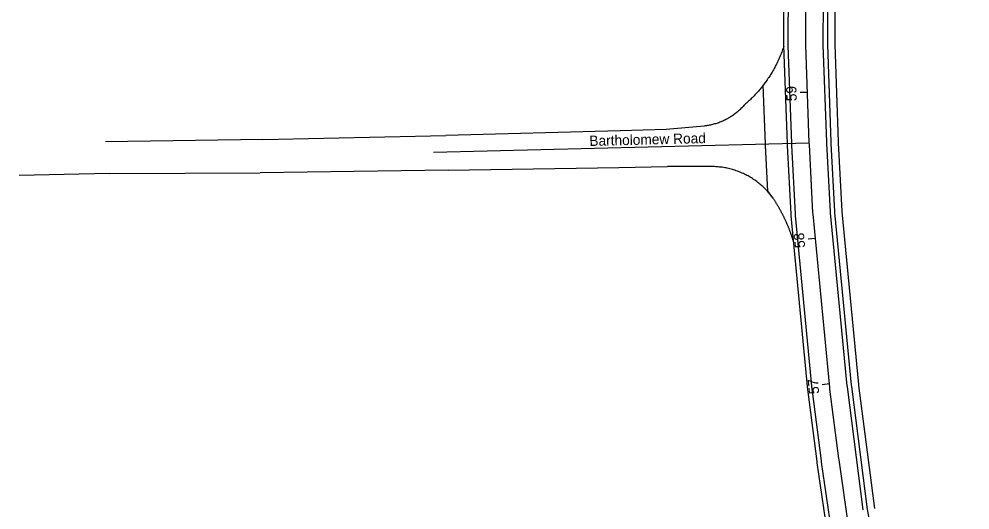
# Model space of a CAD drawing. Extents: x 2318076 to 2324211, y 613525 to 629939.
# Drawn here: x 2318076 to 2318726, y 620517 to 620852 of the extents above; entities that cross this region are included whole.
import ezdxf

# ---------------------------------------------------------------- set-up
doc = ezdxf.new("R2010")
doc.units = 0
for name, color, linetype in [('GE_P_CL_50', 7, 'Continuous'), ('GE_X_CL_50', 7, 'Continuous'), ('PV_P_EOP', 7, 'Continuous'), ('PV_P_Shoulder', 7, 'Continuous'), ('RD_X_GR_Rt', 7, 'Continuous'), ('RS_Raster1', 7, 'Continuous'), ('TX_P_1', 7, 'Continuous')]:
    doc.layers.add(name, color=color, linetype=linetype)

msp = doc.modelspace()

# ---------------------------------------------------------------- linework, layer by layer
at = {"layer": 'GE_P_CL_50'}
for p, q in [((2318615.25, 620802.3), (2318610.26, 620802.12)), ((2318620.66, 620702.47), (2318615.68, 620701.99)), ((2318630.24, 620602.93), (2318625.26, 620602.45))]:
    msp.add_line(p, q, dxfattribs=at)
msp.add_lwpolyline([(2318643.51, 620504.66), (2318636.81, 620551.04), (2318636.68, 620552.01), (2318630.59, 620599.46), (2318630.48, 620600.43), (2318619.07, 620719), (2318619.01, 620719.99), (2318616.54, 620766.75), (2318616.5, 620767.74), (2318614.09, 620834.59), (2318614.09, 620835.59), (2318614.08, 620836.59), (2318614.07, 620837.58), (2318614.09, 620849.48), (2318614.1, 620850.47), (2318614.18, 620857.38)], dxfattribs=at)
at = {"layer": 'GE_X_CL_50'}
msp.add_line((2318359.77, 620761.32), (2318616.5, 620767.74), dxfattribs=at)
at = {"layer": 'PV_P_EOP'}
for points in [[(2318631.64, 620502.89), (2318624.93, 620549.37), (2318624.78, 620550.44), (2318618.68, 620597.98), (2318618.54, 620599.14), (2318607.11, 620718.03), (2318607.03, 620719.28), (2318604.55, 620766.19), (2318604.51, 620767.29), (2318602.1, 620834.32), (2318602.09, 620835.48), (2318602.08, 620836.49), (2318602.07, 620837.55), (2318602.09, 620849.54), (2318602.1, 620850.59), (2318602.18, 620857.53)], [(2318653.3, 620516.78), (2318642.5, 620600.94), (2318642.41, 620601.72), (2318631.03, 620719.97), (2318630.99, 620720.7), (2318628.52, 620767.31), (2318628.49, 620768.2), (2318626.09, 620834.86), (2318626.08, 620835.69), (2318626.08, 620836.68), (2318626.07, 620837.62), (2318626.09, 620849.42), (2318626.1, 620850.35), (2318626.18, 620857.23)], [(2318599.11, 620833.88), (2318598.88, 620833.18), (2318598.59, 620832.34), (2318598.3, 620831.5), (2318597.99, 620830.66), (2318597.68, 620829.83), (2318597.36, 620828.99), (2318597.03, 620828.17), (2318596.69, 620827.34), (2318596.34, 620826.52), (2318595.99, 620825.7), (2318595.63, 620824.89), (2318595.25, 620824.08), (2318594.88, 620823.27), (2318594.49, 620822.47), (2318594.09, 620821.67), (2318593.69, 620820.87), (2318593.28, 620820.08), (2318592.86, 620819.29), (2318592.43, 620818.51), (2318592, 620817.73), (2318591.56, 620816.96), (2318591.11, 620816.19), (2318590.65, 620815.43), (2318590.18, 620814.67), (2318589.71, 620813.91), (2318589.23, 620813.16), (2318588.74, 620812.41), (2318588.24, 620811.67), (2318587.74, 620810.94), (2318585.07, 620807.12)], [(2318588.2, 620734.8), (2318586.55, 620766.05), (2318586.51, 620767.17), (2318585.07, 620807.12)], [(2318591.8, 620729.86), (2318588.2, 620734.8)], [(2318605.83, 620699.99), (2318605.72, 620700.35), (2318605.6, 620700.74), (2318605.48, 620701.12), (2318605.36, 620701.51), (2318605.24, 620701.89), (2318605.11, 620702.28), (2318604.99, 620702.66), (2318604.86, 620703.05), (2318604.73, 620703.43), (2318604.6, 620703.81), (2318604.47, 620704.2), (2318604.34, 620704.58), (2318604.21, 620704.96), (2318604.07, 620705.34), (2318603.94, 620705.72), (2318603.8, 620706.1), (2318603.66, 620706.48), (2318603.52, 620706.86), (2318603.38, 620707.24), (2318603.23, 620707.62), (2318603.09, 620707.99), (2318602.94, 620708.37), (2318602.8, 620708.75), (2318602.65, 620709.12), (2318602.5, 620709.5), (2318602.35, 620709.87), (2318602.19, 620710.25), (2318602.04, 620710.62), (2318601.89, 620711), (2318601.73, 620711.37), (2318601.57, 620711.74), (2318601.41, 620712.11), (2318601.25, 620712.48), (2318601.09, 620712.85), (2318600.93, 620713.22), (2318600.76, 620713.59), (2318600.6, 620713.96), (2318600.43, 620714.33), (2318600.26, 620714.7), (2318600.09, 620715.06), (2318599.92, 620715.43), (2318599.75, 620715.79), (2318599.57, 620716.16), (2318599.4, 620716.52), (2318599.22, 620716.89), (2318599.04, 620717.25), (2318598.86, 620717.61), (2318598.68, 620717.97), (2318598.5, 620718.34), (2318598.32, 620718.7), (2318598.14, 620719.06), (2318597.95, 620719.42), (2318597.76, 620719.77), (2318597.58, 620720.13), (2318597.39, 620720.49), (2318597.2, 620720.85), (2318597, 620721.2), (2318596.81, 620721.56), (2318596.62, 620721.91), (2318596.42, 620722.26), (2318596.22, 620722.62), (2318596.03, 620722.97), (2318595.83, 620723.32), (2318595.63, 620723.67), (2318595.42, 620724.02), (2318595.22, 620724.37), (2318595.02, 620724.72), (2318594.81, 620725.07), (2318594.6, 620725.42), (2318594.39, 620725.76), (2318594.19, 620726.11), (2318593.97, 620726.45), (2318593.76, 620726.8), (2318593.55, 620727.14), (2318593.33, 620727.48), (2318593.12, 620727.82), (2318592.9, 620728.17), (2318592.68, 620728.51), (2318592.47, 620728.85), (2318592.24, 620729.18), (2318592.02, 620729.52), (2318591.8, 620729.86)]]:
    msp.add_lwpolyline(points, dxfattribs=at)
at = {"layer": 'PV_P_Shoulder'}
for points in [[(2318628.67, 620502.45), (2318621.96, 620548.96), (2318621.81, 620550.04), (2318615.71, 620597.61), (2318615.56, 620598.82), (2318604.12, 620717.79), (2318604.03, 620719.11), (2318601.55, 620766.05), (2318601.51, 620767.17), (2318599.1, 620834.25), (2318599.09, 620835.45), (2318599.08, 620836.46), (2318599.07, 620837.54), (2318599.09, 620849.56), (2318599.1, 620850.62), (2318599.18, 620857.57)], [(2318656.27, 620517.16), (2318645.48, 620601.31), (2318645.39, 620602.05), (2318634.02, 620720.21), (2318633.98, 620720.88), (2318631.52, 620767.44), (2318631.49, 620768.31), (2318629.09, 620834.93), (2318629.08, 620835.72), (2318629.08, 620836.71), (2318629.07, 620837.63), (2318629.09, 620849.4), (2318629.1, 620850.32), (2318629.18, 620857.19)], [(2318726.31, 620118.23), (2318656.25, 620517.3)]]:
    msp.add_lwpolyline(points, dxfattribs=at)
at = {"layer": 'RD_X_GR_Rt'}
msp.add_lwpolyline([(2318661.23, 620517.8), (2318650.44, 620601.93), (2318650.36, 620602.58), (2318639.01, 620720.61), (2318638.97, 620721.17), (2318636.52, 620767.68), (2318636.48, 620768.5), (2318634.09, 620835.04), (2318634.08, 620835.77), (2318634.08, 620836.75), (2318634.07, 620837.64), (2318634.09, 620849.38), (2318634.1, 620850.27), (2318634.18, 620857.13)], dxfattribs=at)
at = {"layer": 'RS_Raster1'}
for p, q in [((2318544.73, 620779.28), (2318518.65, 620776.96)), ((2318369.82, 620749), (2318486.39, 620751.03)), ((2318486.39, 620751.03), (2318519.51, 620751.7)), ((2318548.09, 620751.54), (2318519.51, 620751.7))]:
    msp.add_line(p, q, dxfattribs=at)
for points in [[(2318599.11, 620833.88), (2318598.88, 620833.18), (2318598.59, 620832.34), (2318598.3, 620831.5), (2318597.99, 620830.66), (2318597.68, 620829.83), (2318597.36, 620828.99), (2318597.03, 620828.17), (2318596.69, 620827.34), (2318596.34, 620826.52), (2318595.99, 620825.7), (2318595.63, 620824.89), (2318595.25, 620824.08), (2318594.88, 620823.27), (2318594.49, 620822.47), (2318594.09, 620821.67), (2318593.69, 620820.87), (2318593.28, 620820.08), (2318592.86, 620819.29), (2318592.43, 620818.51), (2318592, 620817.73), (2318591.56, 620816.96), (2318591.11, 620816.19), (2318590.65, 620815.43), (2318590.18, 620814.67), (2318589.71, 620813.91), (2318589.23, 620813.16), (2318588.74, 620812.41), (2318588.24, 620811.67), (2318587.74, 620810.94), (2318587.23, 620810.21), (2318586.71, 620809.48), (2318586.19, 620808.76), (2318585.66, 620808.05), (2318585.12, 620807.34), (2318584.57, 620806.63), (2318584.02, 620805.94), (2318583.46, 620805.24), (2318582.89, 620804.56), (2318582.32, 620803.87), (2318581.74, 620803.2), (2318581.15, 620802.53), (2318580.55, 620801.87), (2318579.95, 620801.21), (2318579.35, 620800.56), (2318578.73, 620799.91), (2318578.11, 620799.27), (2318577.49, 620798.64), (2318576.85, 620798.01), (2318576.21, 620797.39), (2318575.57, 620796.78), (2318574.92, 620796.17), (2318574.26, 620795.57), (2318573.59, 620794.98), (2318572.93, 620794.39), (2318572.25, 620793.81)], [(2318572.25, 620793.81), (2318571.77, 620793.26), (2318571.29, 620792.72), (2318570.8, 620792.19), (2318570.29, 620791.67), (2318569.78, 620791.15), (2318569.26, 620790.65), (2318568.73, 620790.15), (2318568.2, 620789.67), (2318567.65, 620789.19), (2318567.1, 620788.72), (2318566.53, 620788.26), (2318565.96, 620787.81), (2318565.39, 620787.37), (2318564.8, 620786.95), (2318564.21, 620786.53), (2318563.61, 620786.12), (2318563.01, 620785.72), (2318562.39, 620785.33), (2318561.77, 620784.96), (2318561.15, 620784.59), (2318560.52, 620784.24), (2318559.88, 620783.89), (2318559.23, 620783.56), (2318558.58, 620783.24), (2318557.93, 620782.93), (2318557.27, 620782.63), (2318556.61, 620782.34), (2318555.94, 620782.07), (2318555.26, 620781.8), (2318554.58, 620781.55), (2318553.9, 620781.31), (2318553.21, 620781.08), (2318552.52, 620780.86), (2318551.83, 620780.66), (2318551.13, 620780.47), (2318550.43, 620780.28), (2318549.72, 620780.12), (2318549.02, 620779.96), (2318548.31, 620779.82), (2318547.6, 620779.68), (2318546.88, 620779.56), (2318546.17, 620779.46), (2318545.45, 620779.36), (2318544.73, 620779.28)], [(2318518.65, 620776.96), (2318487.18, 620775.88), (2318368.13, 620772.81)], [(2318591.8, 620729.86), (2318591.28, 620730.58), (2318590.74, 620731.29), (2318590.19, 620731.99), (2318589.63, 620732.69), (2318589.05, 620733.37), (2318588.47, 620734.04), (2318587.87, 620734.7), (2318587.27, 620735.36), (2318586.65, 620736), (2318586.02, 620736.63), (2318585.38, 620737.25), (2318584.73, 620737.86), (2318584.07, 620738.46), (2318583.4, 620739.04), (2318582.72, 620739.62), (2318582.02, 620740.18), (2318581.32, 620740.73), (2318580.61, 620741.27), (2318579.9, 620741.8), (2318579.17, 620742.31), (2318578.43, 620742.81), (2318577.69, 620743.3), (2318576.93, 620743.78), (2318576.17, 620744.24), (2318575.4, 620744.69), (2318574.62, 620745.13), (2318573.84, 620745.55), (2318573.05, 620745.96), (2318572.25, 620746.36), (2318571.45, 620746.74), (2318570.63, 620747.11), (2318569.82, 620747.46), (2318568.99, 620747.8), (2318568.16, 620748.13), (2318567.33, 620748.44), (2318566.49, 620748.74), (2318565.64, 620749.02), (2318564.79, 620749.29), (2318563.94, 620749.54), (2318563.08, 620749.78), (2318562.22, 620750), (2318561.35, 620750.21), (2318560.48, 620750.41), (2318559.61, 620750.59), (2318558.73, 620750.75), (2318557.86, 620750.9), (2318556.98, 620751.04), (2318556.09, 620751.15), (2318555.21, 620751.26), (2318554.32, 620751.35), (2318553.43, 620751.42), (2318552.54, 620751.48), (2318551.65, 620751.52), (2318550.76, 620751.55), (2318549.87, 620751.56), (2318548.98, 620751.56), (2318548.09, 620751.54)], [(2318605.83, 620699.99), (2318605.72, 620700.35), (2318605.6, 620700.74), (2318605.48, 620701.12), (2318605.36, 620701.51), (2318605.24, 620701.89), (2318605.11, 620702.28), (2318604.99, 620702.66), (2318604.86, 620703.05), (2318604.73, 620703.43), (2318604.6, 620703.81), (2318604.47, 620704.2), (2318604.34, 620704.58), (2318604.21, 620704.96), (2318604.07, 620705.34), (2318603.94, 620705.72), (2318603.8, 620706.1), (2318603.66, 620706.48), (2318603.52, 620706.86), (2318603.38, 620707.24), (2318603.23, 620707.62), (2318603.09, 620707.99), (2318602.94, 620708.37), (2318602.8, 620708.75), (2318602.65, 620709.12), (2318602.5, 620709.5), (2318602.35, 620709.87), (2318602.19, 620710.25), (2318602.04, 620710.62), (2318601.89, 620711), (2318601.73, 620711.37), (2318601.57, 620711.74), (2318601.41, 620712.11), (2318601.25, 620712.48), (2318601.09, 620712.85), (2318600.93, 620713.22), (2318600.76, 620713.59), (2318600.6, 620713.96), (2318600.43, 620714.33), (2318600.26, 620714.7), (2318600.09, 620715.06), (2318599.92, 620715.43), (2318599.75, 620715.79), (2318599.57, 620716.16), (2318599.4, 620716.52), (2318599.22, 620716.89), (2318599.04, 620717.25), (2318598.86, 620717.61), (2318598.68, 620717.97), (2318598.5, 620718.34), (2318598.32, 620718.7), (2318598.14, 620719.06), (2318597.95, 620719.42), (2318597.76, 620719.77), (2318597.58, 620720.13), (2318597.39, 620720.49), (2318597.2, 620720.85), (2318597, 620721.2), (2318596.81, 620721.56), (2318596.62, 620721.91), (2318596.42, 620722.26), (2318596.22, 620722.62), (2318596.03, 620722.97), (2318595.83, 620723.32), (2318595.63, 620723.67), (2318595.42, 620724.02), (2318595.22, 620724.37), (2318595.02, 620724.72), (2318594.81, 620725.07), (2318594.6, 620725.42), (2318594.39, 620725.76), (2318594.19, 620726.11), (2318593.97, 620726.45), (2318593.76, 620726.8), (2318593.55, 620727.14), (2318593.33, 620727.48), (2318593.12, 620727.82), (2318592.9, 620728.17), (2318592.68, 620728.51), (2318592.47, 620728.85), (2318592.24, 620729.18), (2318592.02, 620729.52), (2318591.8, 620729.86)]]:
    msp.add_lwpolyline(points, dxfattribs=at)
at = {"layer": 'TX_P_1'}
for p, q in [((2318243.08, 620770.14), (2318135.63, 620768.53)), ((2318243.08, 620770.14), (2318368.13, 620772.81)), ((2318369.82, 620749), (2318241.25, 620747.36)), ((2318138.14, 620746.79), (2318076.45, 620745.46)), ((2318138.14, 620746.79), (2318241.25, 620747.36))]:
    msp.add_line(p, q, dxfattribs=at)

# ---------------------------------------------------------------- texts
at = {"layer": 'GE_P_CL_50'}
for s, rotation, p in [('59', 92.05824, (2318607.96, 620796.36)), ('Bartholomew Road', 1.43864, (2318466.3, 620765.61)), ('58', 95.49409, (2318613.73, 620696.21)), ('57', 95.49409, (2318623.33, 620596.37))]:
    msp.add_text(s, height=7, rotation=rotation, dxfattribs=at).set_placement(p)

doc.saveas('drawing.dxf')
